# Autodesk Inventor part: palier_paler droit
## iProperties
Created: 2011-01
Part Number: palier_paler droit
Document SubType Name: Modeling
Designer: eric
Density: 1 g/cm^3
Mass: 10.9593 g
Surface Area: 60.7956 cm^2
Volume: 10.9593 cm^3
Author: eric
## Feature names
1. Base1
